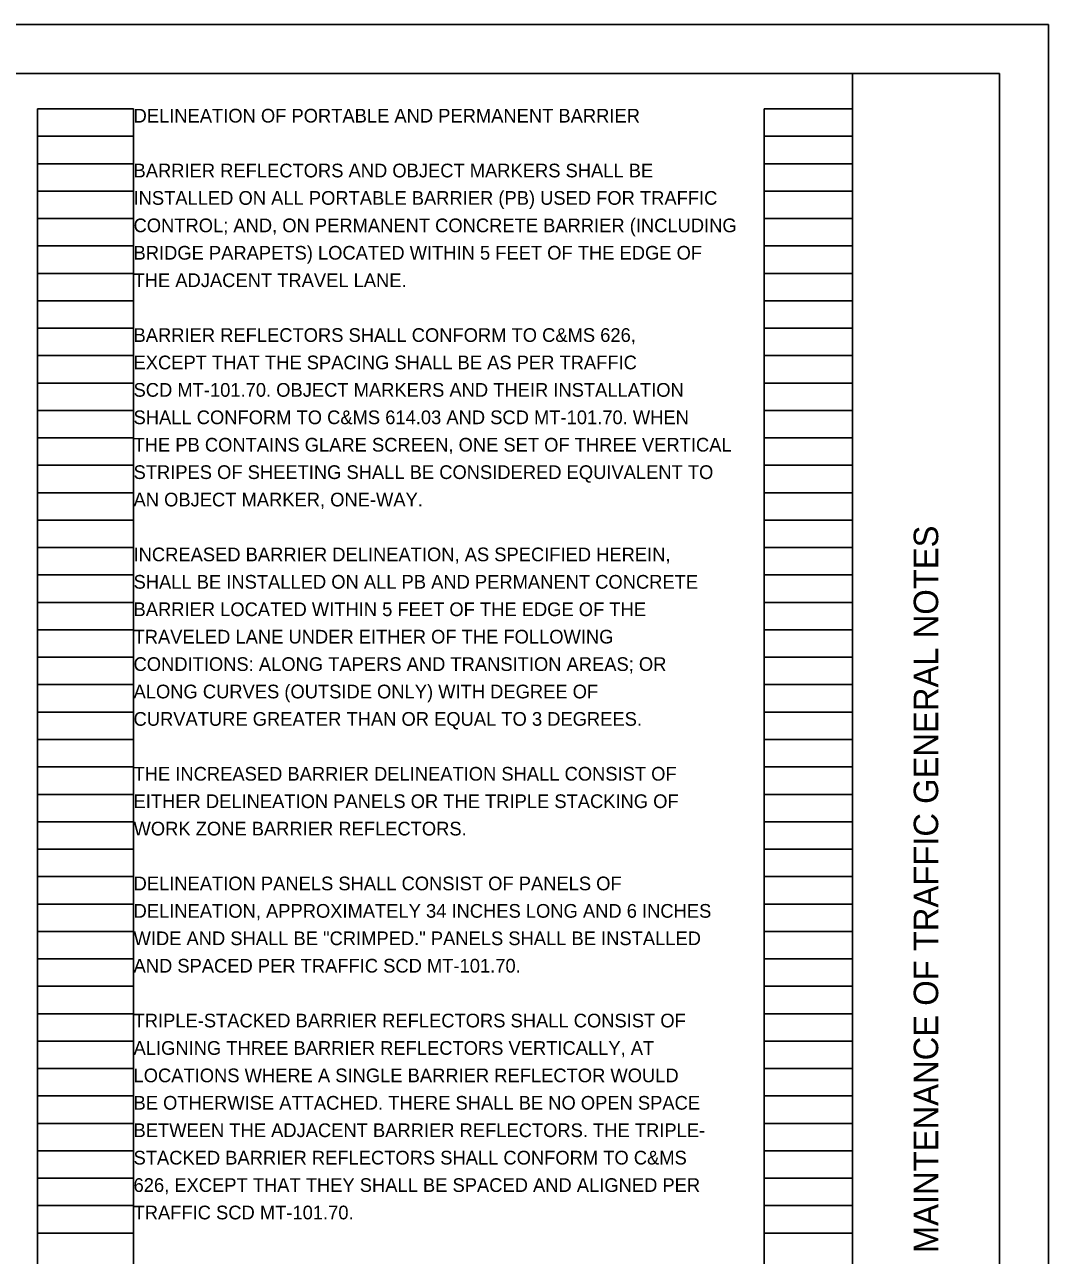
# Model space of a CAD drawing. Extents: x 0 to 40, y 0 to 22.
# Drawn here: x 23.55 to 34, y 9.43 to 22 of the extents above; entities that cross this region are included whole.
import ezdxf

# ---------------------------------------------------------------- set-up
doc = ezdxf.new("R2010")
doc.units = 0
for name, color, linetype in [('SH_Border', 7, 'Continuous'), ('SH_Cut_Line', 7, 'Continuous'), ('SH_Data', 7, 'Continuous'), ('SH_Text', 7, 'Continuous')]:
    doc.layers.add(name, color=color, linetype=linetype)

msp = doc.modelspace()

# ---------------------------------------------------------------- linework, layer by layer
at = {"layer": 'SH_Border'}
msp.add_line((32, 0.5), (32, 21.5), dxfattribs=at)
msp.add_lwpolyline([(1.5, 21.5), (33.5, 21.5), (33.5, 0.5), (1.5, 0.5)], close=True, dxfattribs=at)
at = {"layer": 'SH_Cut_Line'}
msp.add_lwpolyline([(0, 0), (34, 0), (34, 22), (0, 22)], close=True, dxfattribs=at)
at = {"layer": 'SH_Data'}
for p, q in [((23.68, 0.98), (23.68, 21.14)), ((23.68, 21.14), (24.66, 21.14)), ((24.66, 0.98), (24.66, 21.14)), ((31.1, 0.98), (31.1, 21.14)), ((31.1, 21.14), (32, 21.14)), ((32, 0.98), (32, 21.14)), ((23.68, 20.86), (24.66, 20.86)), ((31.1, 20.86), (32, 20.86)), ((23.68, 20.58), (24.66, 20.58)), ((31.1, 20.58), (32, 20.58)), ((23.68, 20.3), (24.66, 20.3)), ((31.1, 20.3), (32, 20.3)), ((23.68, 20.02), (24.66, 20.02)), ((31.1, 20.02), (32, 20.02)), ((23.68, 19.74), (24.66, 19.74)), ((31.1, 19.74), (32, 19.74)), ((23.68, 19.46), (24.66, 19.46)), ((31.1, 19.46), (32, 19.46)), ((23.68, 19.18), (24.66, 19.18)), ((31.1, 19.18), (32, 19.18)), ((23.68, 18.9), (24.66, 18.9)), ((31.1, 18.9), (32, 18.9)), ((23.68, 18.62), (24.66, 18.62)), ((31.1, 18.62), (32, 18.62)), ((23.68, 18.34), (24.66, 18.34)), ((31.1, 18.34), (32, 18.34)), ((23.68, 18.06), (24.66, 18.06)), ((31.1, 18.06), (32, 18.06)), ((23.68, 17.78), (24.66, 17.78)), ((31.1, 17.78), (32, 17.78)), ((23.68, 17.5), (24.66, 17.5)), ((31.1, 17.5), (32, 17.5)), ((23.68, 17.22), (24.66, 17.22)), ((31.1, 17.22), (32, 17.22)), ((23.68, 16.94), (24.66, 16.94)), ((31.1, 16.94), (32, 16.94)), ((23.68, 16.66), (24.66, 16.66)), ((31.1, 16.66), (32, 16.66)), ((23.68, 16.38), (24.66, 16.38)), ((31.1, 16.38), (32, 16.38)), ((23.68, 16.1), (24.66, 16.1)), ((31.1, 16.1), (32, 16.1)), ((23.68, 15.82), (24.66, 15.82)), ((31.1, 15.82), (32, 15.82)), ((23.68, 15.54), (24.66, 15.54)), ((31.1, 15.54), (32, 15.54)), ((23.68, 15.26), (24.66, 15.26)), ((31.1, 15.26), (32, 15.26)), ((23.68, 14.98), (24.66, 14.98)), ((31.1, 14.98), (32, 14.98)), ((23.68, 14.7), (24.66, 14.7)), ((31.1, 14.7), (32, 14.7)), ((23.68, 14.42), (24.66, 14.42)), ((31.1, 14.42), (32, 14.42)), ((23.68, 14.14), (24.66, 14.14)), ((31.1, 14.14), (32, 14.14)), ((23.68, 13.86), (24.66, 13.86)), ((31.1, 13.86), (32, 13.86)), ((23.68, 13.58), (24.66, 13.58)), ((31.1, 13.58), (32, 13.58)), ((23.68, 13.3), (24.66, 13.3)), ((31.1, 13.3), (32, 13.3)), ((23.68, 13.02), (24.66, 13.02)), ((31.1, 13.02), (32, 13.02)), ((23.68, 12.74), (24.66, 12.74)), ((31.1, 12.74), (32, 12.74)), ((23.68, 12.46), (24.66, 12.46)), ((31.1, 12.46), (32, 12.46)), ((23.68, 12.18), (24.66, 12.18)), ((31.1, 12.18), (32, 12.18)), ((23.68, 11.9), (24.66, 11.9)), ((31.1, 11.9), (32, 11.9)), ((23.68, 11.62), (24.66, 11.62)), ((31.1, 11.62), (32, 11.62)), ((23.68, 11.34), (24.66, 11.34)), ((31.1, 11.34), (32, 11.34)), ((23.68, 11.06), (24.66, 11.06)), ((31.1, 11.06), (32, 11.06)), ((23.68, 10.78), (24.66, 10.78)), ((31.1, 10.78), (32, 10.78)), ((23.68, 10.5), (24.66, 10.5)), ((31.1, 10.5), (32, 10.5)), ((23.68, 10.22), (24.66, 10.22)), ((31.1, 10.22), (32, 10.22)), ((23.68, 9.94), (24.66, 9.94)), ((31.1, 9.94), (32, 9.94)), ((23.68, 9.66), (24.66, 9.66)), ((31.1, 9.66), (32, 9.66))]:
    msp.add_line(p, q, dxfattribs=at)

# ---------------------------------------------------------------- texts
msp.add_text('MAINTENANCE OF TRAFFIC GENERAL NOTES', height=0.25, rotation=90, dxfattribs=at).set_placement((32.875, 9.455))
at = {"layer": 'SH_Text'}
for s, p in [('DELINEATION OF PORTABLE AND PERMANENT BARRIER', (24.66, 21)), ('BARRIER REFLECTORS AND OBJECT MARKERS SHALL BE', (24.66, 20.44)), ('INSTALLED ON ALL PORTABLE BARRIER (PB) USED FOR TRAFFIC', (24.66, 20.16)), ('CONTROL; AND, ON PERMANENT CONCRETE BARRIER (INCLUDING', (24.66, 19.88)), ('BRIDGE PARAPETS) LOCATED WITHIN 5 FEET OF THE EDGE OF', (24.66, 19.6)), ('THE ADJACENT TRAVEL LANE.', (24.66, 19.32)), ('BARRIER REFLECTORS SHALL CONFORM TO C&MS 626,', (24.66, 18.76)), ('EXCEPT THAT THE SPACING SHALL BE AS PER TRAFFIC', (24.66, 18.48)), ('SCD MT-101.70. OBJECT MARKERS AND THEIR INSTALLATION', (24.66, 18.2)), ('SHALL CONFORM TO C&MS 614.03 AND SCD MT-101.70. WHEN', (24.66, 17.92)), ('THE PB CONTAINS GLARE SCREEN, ONE SET OF THREE VERTICAL', (24.66, 17.64)), ('STRIPES OF SHEETING SHALL BE CONSIDERED EQUIVALENT TO', (24.66, 17.36)), ('AN OBJECT MARKER, ONE-WAY.', (24.66, 17.08)), ('INCREASED BARRIER DELINEATION, AS SPECIFIED HEREIN,', (24.66, 16.52)), ('SHALL BE INSTALLED ON ALL PB AND PERMANENT CONCRETE', (24.66, 16.24)), ('BARRIER LOCATED WITHIN 5 FEET OF THE EDGE OF THE', (24.66, 15.96)), ('TRAVELED LANE UNDER EITHER OF THE FOLLOWING', (24.66, 15.68)), ('CONDITIONS: ALONG TAPERS AND TRANSITION AREAS; OR', (24.66, 15.4)), ('ALONG CURVES (OUTSIDE ONLY) WITH DEGREE OF', (24.66, 15.12)), ('CURVATURE GREATER THAN OR EQUAL TO 3 DEGREES.', (24.66, 14.84)), ('THE INCREASED BARRIER DELINEATION SHALL CONSIST OF', (24.66, 14.28)), ('EITHER DELINEATION PANELS OR THE TRIPLE STACKING OF', (24.66, 14)), ('WORK ZONE BARRIER REFLECTORS.', (24.66, 13.72)), ('DELINEATION PANELS SHALL CONSIST OF PANELS OF', (24.66, 13.16)), ('DELINEATION, APPROXIMATELY 34 INCHES LONG AND 6 INCHES', (24.66, 12.88)), ('WIDE AND SHALL BE "CRIMPED." PANELS SHALL BE INSTALLED', (24.66, 12.6)), ('AND SPACED PER TRAFFIC SCD MT-101.70.', (24.66, 12.32)), ('TRIPLE-STACKED BARRIER REFLECTORS SHALL CONSIST OF', (24.66, 11.76)), ('ALIGNING THREE BARRIER REFLECTORS VERTICALLY, AT', (24.66, 11.48)), ('LOCATIONS WHERE A SINGLE BARRIER REFLECTOR WOULD', (24.66, 11.2)), ('BE OTHERWISE ATTACHED. THERE SHALL BE NO OPEN SPACE', (24.66, 10.92)), ('BETWEEN THE ADJACENT BARRIER REFLECTORS. THE TRIPLE-', (24.66, 10.64)), ('STACKED BARRIER REFLECTORS SHALL CONFORM TO C&MS', (24.66, 10.36)), ('626, EXCEPT THAT THEY SHALL BE SPACED AND ALIGNED PER', (24.66, 10.08)), ('TRAFFIC SCD MT-101.70.', (24.66, 9.8))]:
    msp.add_text(s, height=0.14, dxfattribs=at).set_placement(p)

doc.saveas('drawing.dxf')
